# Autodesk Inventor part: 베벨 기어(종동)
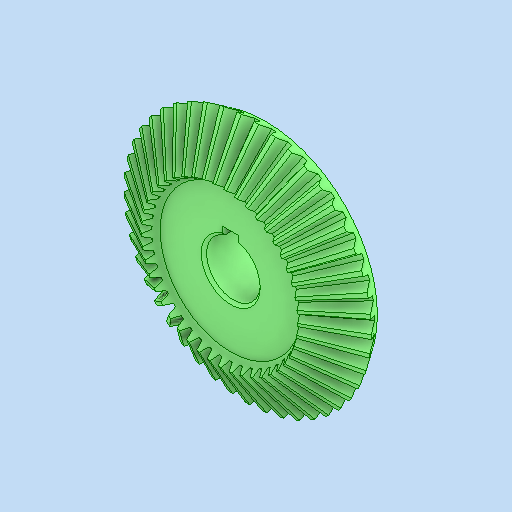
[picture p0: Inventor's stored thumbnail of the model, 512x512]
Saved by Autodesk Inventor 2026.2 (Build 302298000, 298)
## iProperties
Created: 2026-01
Part Number: 베벨 기어(종동)
Material: 강철, 합금
Document SubType Name: Modeling
Designer: PC2-07
Density: 7.73 g/cm^3
Appearance: 기본값
Author: jhkim
Sending System: Autodesk Inventor 2026
Preprocessor: ST-DEVELOPER v20.1
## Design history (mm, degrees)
feature "Solid1"
node "솔리드1"
